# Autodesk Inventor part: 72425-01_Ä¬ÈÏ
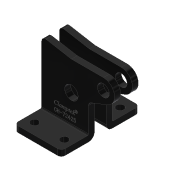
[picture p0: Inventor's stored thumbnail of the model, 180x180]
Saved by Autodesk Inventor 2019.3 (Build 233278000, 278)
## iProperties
Created: 2010-06
Part Number: 72425-01_Ä¬ÈÏ
Material: Ogólny
Document SubType Name: Modeling
Designer: CADENGINEERING4
Density: 1 g/cm^3
Appearance: Gładki — czarny
Author: CADENGINEERING4
Revision Number: ÈÎºÎ
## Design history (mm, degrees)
feature "NONE"
feature "NONE:1"
node "Bryła1"
node "Bryła2"
